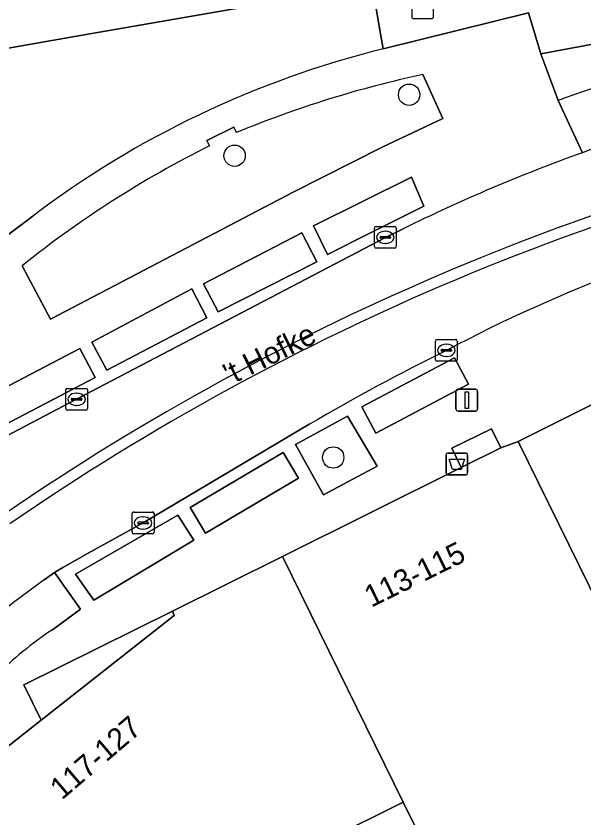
# Model space of a CAD drawing. Extents: x 162879 to 165540, y 384011 to 385181.
# Drawn here: x 164083.04 to 164109.04, y 384464.13 to 384500.81 of the extents above; entities that cross this region are included whole.
import ezdxf

# ---------------------------------------------------------------- set-up
doc = ezdxf.new("R2010")
doc.units = 0
for name, color, linetype in [('IMGEO_Afvalbak', 7, 'Continuous'), ('IMGEO_Boom', 7, 'Continuous'), ('IMGEO_Erf', 7, 'Continuous'), ('IMGEO_Groenvoorziening', 7, 'Continuous'), ('IMGEO_Kolk', 7, 'Continuous'), ('IMGEO_Lichtmast', 7, 'Continuous'), ('IMGEO_Openbare_ruimte_label', 7, 'Continuous'), ('IMGEO_Pand', 7, 'Continuous'), ('IMGEO_Pand_nummerreeks', 7, 'Continuous'), ('IMGEO_Pand_overbouw', 7, 'Continuous'), ('IMGEO_Parkeervlak_open', 7, 'Continuous'), ('IMGEO_Poller', 7, 'Continuous'), ('IMGEO_Rijbaan_lokaal_gesloten', 7, 'Continuous'), ('IMGEO_Rijbaan_lokaal_open', 7, 'Continuous'), ('IMGEO_Voetpad_open', 7, 'Continuous')]:
    doc.layers.add(name, color=color, linetype=linetype)

msp = doc.modelspace()

# ---------------------------------------------------------------- linework, layer by layer
at = {"layer": 'IMGEO_Afvalbak'}
for p, q in [((164102.726, 384479.923), (164102.726, 384480.723)), ((164102.726, 384480.723), (164102.726, 384479.923)), ((164102.826, 384480.823), (164103.616, 384480.823)), ((164103.616, 384480.823), (164102.826, 384480.823)), ((164103.716, 384480.723), (164103.716, 384479.923)), ((164103.716, 384479.923), (164103.716, 384480.723)), ((164103.616, 384479.823), (164102.826, 384479.823)), ((164102.826, 384479.823), (164103.616, 384479.823))]:
    msp.add_line(p, q, dxfattribs=at)
msp.add_lwpolyline([(164102.869, 384480.537), (164103.573, 384480.537), (164103.424, 384480.067), (164103.018, 384480.067), (164102.869, 384480.537)], dxfattribs=at)
for centre, start, end in [((164102.826, 384480.723), 90, 180), ((164102.826, 384480.723), 90, 180), ((164103.616, 384480.723), 0, 90), ((164103.616, 384480.723), 360, 90), ((164102.826, 384479.923), 180, 270), ((164102.826, 384479.923), 180, 270), ((164103.616, 384479.923), 270, 0), ((164103.616, 384479.923), 270, 0)]:
    msp.add_arc(centre, 0.1, start, end, dxfattribs=at)
at = {"layer": 'IMGEO_Boom'}
for centre in [(164101.039, 384497.213), (164093.047, 384494.422), (164097.562, 384480.618)]:
    msp.add_circle(centre, 0.489, dxfattribs=at)
at = {"layer": 'IMGEO_Erf'}
for points in [[(164099.846, 384499.31), (164099.728, 384500), (164096.988, 384516.038), (164096.451, 384515.965), (164098.837, 384502.169), (164086.427, 384500), (164076.77, 384498.312), (164077.06, 384496.833), (164073.548, 384494.062), (164079.048, 384490.02), (164080.722, 384491.873), (164082.275, 384490.508), (164083.808, 384491.663)], [(164104.315, 384457.699), (164100.767, 384464.846), (164093.655, 384461.316)]]:
    msp.add_lwpolyline(points, dxfattribs=at)
msp.add_arc((164110.43, 384456.471), 44.127, 103.8776, 127.1065, dxfattribs=at)
at = {"layer": 'IMGEO_Groenvoorziening'}
for points in [[(164119.508, 384500.11), (164119.28, 384501.365), (164107.065, 384499.079)], [(164107.065, 384499.079), (164107.867, 384496.956)], [(164084.62, 384486.95), (164095.737, 384492.755), (164099.806, 384494.82), (164102.58, 384496.132), (164101.668, 384498.136)], [(164093.138, 384495.481), (164093.014, 384495.726), (164091.778, 384495.123), (164091.906, 384494.876)], [(164083.322, 384489.384), (164084.62, 384486.95)], [(164084.807, 384475.359), (164084.33, 384475.022)], [(164084.714, 384472.739), (164085.996, 384473.68), (164084.807, 384475.359)]]:
    msp.add_lwpolyline(points, dxfattribs=at)
for points in [[(164101.715, 384492.119), (164101.149, 384493.443), (164096.663, 384491.211), (164097.295, 384489.901), (164099.277, 384490.9)], [(164097.117, 384478.912), (164099.578, 384480.214), (164098.21, 384482.512), (164095.832, 384481.212)]]:
    msp.add_lwpolyline(points, close=True, dxfattribs=at)
for centre, radius, start, end in [((164131.959, 384431.095), 70.129, 100.22681, 110.0926), ((164111.855, 384450.377), 48.834, 102.0408, 112.5372), ((164112.986, 384452.474), 47.353, 116.4338, 128.788), ((164106.482, 384443.885), 38.213, 125.4296, 135.8642), ((164093.11, 384459.914), 15.329, 123.2102, 135.8396)]:
    msp.add_arc(centre, radius, start, end, dxfattribs=at)
at = {"layer": 'IMGEO_Kolk'}
for p, q in [((164099.449, 384490.264), (164099.449, 384491.116)), ((164099.524, 384491.19), (164100.376, 384491.19)), ((164099.937, 384490.97), (164099.962, 384490.97)), ((164100.45, 384491.116), (164100.45, 384490.264)), ((164099.708, 384490.684), (164099.708, 384490.696)), ((164100.146, 384490.647), (164099.748, 384490.647)), ((164099.751, 384490.733), (164100.149, 384490.733)), ((164100.192, 384490.696), (164100.192, 384490.684)), ((164100.376, 384490.19), (164099.524, 384490.19)), ((164099.96, 384490.41), (164099.935, 384490.41)), ((164102.242, 384485.092), (164102.242, 384485.944)), ((164102.317, 384486.018), (164103.169, 384486.018)), ((164102.73, 384485.798), (164102.755, 384485.798)), ((164103.243, 384485.944), (164103.243, 384485.092)), ((164102.501, 384485.512), (164102.501, 384485.524)), ((164102.939, 384485.475), (164102.541, 384485.475)), ((164102.544, 384485.561), (164102.942, 384485.561)), ((164102.985, 384485.524), (164102.985, 384485.512)), ((164103.169, 384485.018), (164102.317, 384485.018)), ((164102.753, 384485.238), (164102.728, 384485.238)), ((164085.317, 384482.854), (164085.317, 384483.706)), ((164085.392, 384483.78), (164086.244, 384483.78)), ((164085.805, 384483.56), (164085.83, 384483.56)), ((164086.318, 384483.706), (164086.318, 384482.854)), ((164085.576, 384483.274), (164085.576, 384483.286)), ((164086.014, 384483.237), (164085.616, 384483.237)), ((164085.619, 384483.323), (164086.017, 384483.323)), ((164086.06, 384483.286), (164086.06, 384483.274)), ((164085.828, 384483), (164085.803, 384483)), ((164086.244, 384482.78), (164085.392, 384482.78)), ((164088.359, 384477.198), (164088.359, 384478.05)), ((164088.434, 384478.124), (164089.286, 384478.124)), ((164089.36, 384478.05), (164089.36, 384477.198)), ((164088.661, 384477.667), (164089.059, 384477.667)), ((164088.847, 384477.904), (164088.872, 384477.904)), ((164088.618, 384477.618), (164088.618, 384477.63)), ((164089.056, 384477.581), (164088.658, 384477.581)), ((164088.87, 384477.344), (164088.845, 384477.344)), ((164089.102, 384477.63), (164089.102, 384477.618)), ((164089.286, 384477.124), (164088.434, 384477.124))]:
    msp.add_line(p, q, dxfattribs=at)
for points in [[(164099.449, 384490.264), (164099.449, 384491.116)], [(164099.524, 384491.19), (164100.376, 384491.19)], [(164100.45, 384491.116), (164100.45, 384490.264)], [(164100.376, 384490.19), (164099.524, 384490.19)], [(164102.242, 384485.092), (164102.242, 384485.944)], [(164102.317, 384486.018), (164103.169, 384486.018)], [(164103.243, 384485.944), (164103.243, 384485.092)], [(164103.169, 384485.018), (164102.317, 384485.018)], [(164085.317, 384482.854), (164085.317, 384483.706)], [(164085.392, 384483.78), (164086.244, 384483.78)], [(164086.318, 384483.706), (164086.318, 384482.854)], [(164086.244, 384482.78), (164085.392, 384482.78)], [(164088.359, 384477.198), (164088.359, 384478.05)], [(164088.434, 384478.124), (164089.286, 384478.124)], [(164089.36, 384478.05), (164089.36, 384477.198)], [(164089.286, 384477.124), (164088.434, 384477.124)]]:
    msp.add_lwpolyline(points, dxfattribs=at)
for centre, radius, start, end in [((164099.526, 384491.114), 0.0765, 91.552, 178.448), ((164099.526, 384491.114), 0.0765, 91.552, 178.448), ((164100.374, 384491.114), 0.0765, 1.552, 88.448), ((164100.374, 384491.114), 0.0765, 1.552, 88.448), ((164099.748, 384490.693), 0.0403, 85.8775, 175.7526), ((164099.745, 384490.683), 0.0366, 178.938, 274.7102), ((164100.149, 384490.69), 0.043, 264.8664, 352.4533), ((164100.153, 384490.695), 0.0386, 1.7309, 96.639), ((164099.526, 384490.266), 0.0765, 181.552, 268.448), ((164099.526, 384490.266), 0.0765, 181.552, 268.448), ((164100.374, 384490.266), 0.0765, 271.552, 358.448), ((164100.374, 384490.266), 0.0765, 271.552, 358.448), ((164102.319, 384485.942), 0.0765, 91.552, 178.448), ((164102.319, 384485.942), 0.0765, 91.552, 178.448), ((164103.167, 384485.942), 0.0765, 1.552, 88.448), ((164103.167, 384485.942), 0.0765, 1.552, 88.448), ((164102.541, 384485.521), 0.0403, 85.8775, 175.7526), ((164102.538, 384485.511), 0.0366, 178.938, 274.7102), ((164102.942, 384485.518), 0.043, 264.8664, 352.4533), ((164102.946, 384485.523), 0.0386, 1.7309, 96.639), ((164102.319, 384485.094), 0.0765, 181.552, 268.448), ((164102.319, 384485.094), 0.0765, 181.552, 268.448), ((164103.167, 384485.094), 0.0765, 271.552, 358.448), ((164103.167, 384485.094), 0.0765, 271.552, 358.448), ((164085.394, 384483.704), 0.0765, 91.552, 178.448), ((164085.394, 384483.704), 0.0765, 91.552, 178.448), ((164086.242, 384483.704), 0.0765, 1.552, 88.448), ((164086.242, 384483.704), 0.0765, 1.552, 88.448), ((164085.616, 384483.283), 0.0403, 85.8775, 175.7526), ((164085.613, 384483.273), 0.0366, 178.938, 274.7102), ((164086.017, 384483.28), 0.043, 264.8664, 352.4533), ((164086.021, 384483.285), 0.0386, 1.7309, 96.639), ((164085.394, 384482.856), 0.0765, 181.552, 268.448), ((164085.394, 384482.856), 0.0765, 181.552, 268.448), ((164086.242, 384482.856), 0.0765, 271.552, 358.448), ((164086.242, 384482.856), 0.0765, 271.552, 358.448), ((164088.436, 384478.048), 0.0765, 91.552, 178.448), ((164088.436, 384478.048), 0.0765, 91.552, 178.448), ((164089.284, 384478.048), 0.0765, 1.552, 88.448), ((164089.284, 384478.048), 0.0765, 1.552, 88.448), ((164088.658, 384477.627), 0.0403, 85.8775, 175.7526), ((164089.063, 384477.629), 0.0386, 1.7309, 96.639), ((164088.655, 384477.617), 0.0366, 178.938, 274.7102), ((164089.059, 384477.624), 0.043, 264.8664, 352.4533), ((164088.436, 384477.2), 0.0765, 181.552, 268.448), ((164088.436, 384477.2), 0.0765, 181.552, 268.448), ((164089.284, 384477.2), 0.0765, 271.552, 358.448), ((164089.284, 384477.2), 0.0765, 271.552, 358.448)]:
    msp.add_arc(centre, radius, start, end, dxfattribs=at)
for centre, major_axis, ratio, start_param, end_param in [((164099.936, 384490.69), (-0.387, 0.002), 0.722429, 4.712389, 7.853982), ((164099.961, 384490.69), (-0.39, 0.002), 0.717154, 1.570796, 4.712389), ((164102.729, 384485.518), (-0.387, 0.002), 0.722429, 4.712389, 7.853982), ((164102.754, 384485.518), (-0.39, 0.002), 0.717154, 1.570796, 4.712389), ((164085.804, 384483.28), (-0.387, 0.002), 0.722429, 4.712389, 7.853982), ((164085.829, 384483.28), (-0.39, 0.002), 0.717154, 1.570796, 4.712389), ((164088.846, 384477.624), (-0.387, 0.002), 0.722429, 4.712389, 7.853982), ((164088.871, 384477.624), (-0.39, 0.002), 0.717154, 1.570796, 4.712389)]:
    msp.add_ellipse(centre, major_axis=major_axis, ratio=ratio, start_param=start_param, end_param=end_param, dxfattribs=at)
at = {"layer": 'IMGEO_Lichtmast'}
for p, q in [((164103.181, 384482.84), (164103.181, 384483.64)), ((164103.181, 384483.64), (164103.181, 384482.84)), ((164103.281, 384483.74), (164104.071, 384483.74)), ((164104.071, 384483.74), (164103.281, 384483.74)), ((164104.171, 384483.64), (164104.171, 384482.84)), ((164104.171, 384482.84), (164104.171, 384483.64)), ((164104.071, 384482.74), (164103.281, 384482.74)), ((164103.281, 384482.74), (164104.071, 384482.74))]:
    msp.add_line(p, q, dxfattribs=at)
msp.add_lwpolyline([(164103.601, 384483.615), (164103.751, 384483.615), (164103.751, 384482.865), (164103.601, 384482.865), (164103.601, 384483.615)], dxfattribs=at)
for centre, start, end in [((164103.281, 384483.64), 90, 180), ((164103.281, 384483.64), 90, 180), ((164104.071, 384483.64), 0, 90), ((164104.071, 384483.64), 360, 90), ((164103.281, 384482.84), 180, 270), ((164103.281, 384482.84), 180, 270), ((164104.071, 384482.84), 270, 0), ((164104.071, 384482.84), 270, 0)]:
    msp.add_arc(centre, 0.1, start, end, dxfattribs=at)
at = {"layer": 'IMGEO_Pand'}
for points in [[(164076.77, 384498.312), (164086.427, 384500), (164098.837, 384502.169), (164096.451, 384515.965), (164093.509, 384515.415), (164093.89, 384513.546), (164077.184, 384510.646), (164070.33, 384509.456), (164070.393, 384509.093), (164071.977, 384500), (164072.362, 384497.789), (164072.404, 384497.549)], [(164095.246, 384476.092), (164100.767, 384464.846), (164104.315, 384457.699), (164116.14, 384463.569), (164110.825, 384474.323), (164109.759, 384473.791), (164106.025, 384481.355), (164105.235, 384481.061), (164103.422, 384480.161)], [(164095.046, 384452.059), (164089.995, 384462.234), (164092.565, 384463.51), (164093.655, 384461.316), (164100.767, 384464.846), (164095.246, 384476.092), (164090.203, 384473.589), (164090.286, 384473.393), (164084.202, 384468.608), (164081.227, 384466.269), (164081.4, 384465.909), (164080.878, 384465.649), (164081.604, 384464.184), (164079.608, 384463.197), (164082.653, 384451.818), (164083.416, 384448.962)]]:
    msp.add_lwpolyline(points, close=True, dxfattribs=at)
at = {"layer": 'IMGEO_Pand_overbouw'}
msp.add_lwpolyline([(164084.202, 384468.608), (164090.286, 384473.393), (164090.203, 384473.589), (164083.402, 384470.224)], close=True, dxfattribs=at)
at = {"layer": 'IMGEO_Parkeervlak_open'}
for points in [[(164096.12, 384490.897), (164091.627, 384488.568), (164092.294, 384487.284), (164096.81, 384489.565)], [(164091.781, 384487.005), (164091.086, 384488.334), (164086.514, 384485.898), (164087.2, 384484.608)], [(164081.464, 384483.256), (164082.134, 384481.921), (164086.662, 384484.271), (164085.971, 384485.602)], [(164103.757, 384483.971), (164103.122, 384485.174), (164098.878, 384482.932), (164099.513, 384481.729)], [(164095.279, 384480.84), (164091.02, 384478.323), (164091.712, 384477.152), (164095.971, 384479.669)], [(164086.609, 384474.089), (164091.187, 384476.831), (164090.451, 384477.975), (164085.762, 384475.286)]]:
    msp.add_lwpolyline(points, close=True, dxfattribs=at)
at = {"layer": 'IMGEO_Poller'}
for p, q in [((164101.157, 384501.598), (164101.157, 384500.791)), ((164101.157, 384501.598), (164101.157, 384500.791)), ((164102.153, 384500.791), (164102.153, 384501.598)), ((164102.153, 384500.791), (164102.153, 384501.598)), ((164101.251, 384500.696), (164102.059, 384500.696)), ((164101.251, 384500.696), (164102.059, 384500.696))]:
    msp.add_line(p, q, dxfattribs=at)
for centre, start, end in [((164101.251, 384500.791), 180, 270), ((164101.251, 384500.791), 180, 270), ((164102.059, 384500.791), 270, 0), ((164102.059, 384500.791), 270, 0)]:
    msp.add_arc(centre, 0.0946, start, end, dxfattribs=at)
at = {"layer": 'IMGEO_Rijbaan_lokaal_gesloten'}
for points in [[(164100.758, 384491.073), (164099.95, 384490.69), (164085.818, 384483.28), (164081.711, 384481.132), (164079.691, 384480.076)], [(164084.33, 384475.022), (164084.807, 384475.359), (164085.219, 384475.594), (164086.352, 384476.247), (164088.86, 384477.624), (164096.5, 384482.153)]]:
    msp.add_lwpolyline(points, dxfattribs=at)
for centre, radius, start, end in [((164147.723, 384382.935), 115.303, 101.15181, 124.45379), ((164147.171, 384384.062), 113.554, 100.98769, 124.55292), ((164135.169, 384421.663), 77.466, 108.54321, 109.76939), ((164135.463, 384420.84), 78.34, 109.76871, 116.29617), ((164135.506, 384423.55), 70.096, 103.08436, 117.8656), ((164148.621, 384392.929), 103.332, 116.35821, 120.29145), ((164106.482, 384443.885), 38.213, 125.4296, 135.8642)]:
    msp.add_arc(centre, radius, start, end, dxfattribs=at)
at = {"layer": 'IMGEO_Rijbaan_lokaal_open'}
msp.add_lwpolyline([(164119.047, 384466.705), (164117.994, 384466.52), (164112.445, 384477.691), (164109.594, 384483.138), (164106.025, 384481.355), (164109.759, 384473.791), (164110.825, 384474.323), (164116.14, 384463.569), (164104.315, 384457.699), (164105.63, 384454.833), (164120.011, 384458.704)], close=True, dxfattribs=at)
for centre, radius, start, end in [((164147.723, 384382.935), 115.303, 101.15181, 124.45379), ((164147.171, 384384.062), 113.554, 100.98769, 124.55292)]:
    msp.add_arc(centre, radius, start, end, dxfattribs=at)
at = {"layer": 'IMGEO_Voetpad_open'}
for points in [[(164096.988, 384516.038), (164099.728, 384500), (164099.846, 384499.31), (164106.497, 384500.959)], [(164106.497, 384500.959), (164107.065, 384499.079), (164119.28, 384501.365), (164119.508, 384500.11)], [(164107.867, 384496.956), (164107.065, 384499.079), (164106.497, 384500.959), (164099.846, 384499.31)], [(164101.668, 384498.136), (164102.58, 384496.132), (164099.806, 384494.82), (164095.737, 384492.755), (164084.62, 384486.95)], [(164108.967, 384494.563), (164107.867, 384496.956)], [(164107.867, 384496.956), (164108.967, 384494.563)], [(164091.906, 384494.876), (164091.778, 384495.123), (164093.014, 384495.726), (164093.138, 384495.481)], [(164083.808, 384491.663), (164082.275, 384490.508), (164080.633, 384488.889), (164079.047, 384486.941), (164075.059, 384483.197)], [(164066.822, 384471.709), (164069.712, 384474.018), (164068.354, 384476.445), (164080.706, 384482.968), (164081.711, 384481.132), (164085.818, 384483.28), (164099.95, 384490.69), (164100.758, 384491.073)], [(164084.62, 384486.95), (164083.322, 384489.384)], [(164082.113, 384470.593), (164079.11, 384467.513), (164077.48, 384468.756), (164075.268, 384466.013), (164077.724, 384463.522), (164078.385, 384464.04), (164081.227, 384466.269), (164084.202, 384468.608), (164083.402, 384470.224), (164090.203, 384473.589), (164095.246, 384476.092), (164103.422, 384480.161), (164102.988, 384481.042), (164104.804, 384481.935), (164105.235, 384481.061), (164106.025, 384481.355), (164109.594, 384483.138)], [(164096.5, 384482.153), (164088.86, 384477.624), (164086.352, 384476.247), (164085.219, 384475.594), (164084.807, 384475.359), (164085.996, 384473.68), (164084.714, 384472.739)]]:
    msp.add_lwpolyline(points, dxfattribs=at)
for points in [[(164096.663, 384491.211), (164101.149, 384493.443), (164101.715, 384492.119), (164099.277, 384490.9), (164097.295, 384489.901)], [(164096.12, 384490.897), (164096.81, 384489.565), (164092.294, 384487.284), (164091.627, 384488.568)], [(164091.781, 384487.005), (164087.2, 384484.608), (164086.514, 384485.898), (164091.086, 384488.334)], [(164086.662, 384484.271), (164082.134, 384481.921), (164081.464, 384483.256), (164085.971, 384485.602)], [(164098.878, 384482.932), (164103.122, 384485.174), (164103.757, 384483.971), (164099.513, 384481.729)], [(164097.117, 384478.912), (164095.832, 384481.212), (164098.21, 384482.512), (164099.578, 384480.214)], [(164103.422, 384480.161), (164105.235, 384481.061), (164104.804, 384481.935), (164102.988, 384481.042)], [(164091.712, 384477.152), (164091.02, 384478.323), (164095.279, 384480.84), (164095.971, 384479.669)], [(164086.609, 384474.089), (164085.762, 384475.286), (164090.451, 384477.975), (164091.187, 384476.831)], [(164083.402, 384470.224), (164084.202, 384468.608), (164090.286, 384473.393), (164090.203, 384473.589)]]:
    msp.add_lwpolyline(points, close=True, dxfattribs=at)
for centre, radius, start, end in [((164131.959, 384431.095), 70.129, 100.22681, 110.0926), ((164110.43, 384456.471), 44.127, 103.8776, 127.1065), ((164111.855, 384450.377), 48.834, 102.0408, 112.5372), ((164135.169, 384421.663), 77.466, 108.54321, 109.76939), ((164112.986, 384452.474), 47.353, 116.4338, 128.788), ((164135.463, 384420.84), 78.34, 109.76871, 116.29617), ((164135.506, 384423.55), 70.096, 103.08436, 117.8656), ((164148.621, 384392.929), 103.332, 116.35821, 120.29145), ((164093.11, 384459.914), 15.329, 123.2102, 135.8396)]:
    msp.add_arc(centre, radius, start, end, dxfattribs=at)

# ---------------------------------------------------------------- texts
at = {"layer": 'IMGEO_Openbare_ruimte_label'}
msp.add_text("'t Hofke", height=1, rotation=26.4882, dxfattribs=at).set_placement((164092.855, 384483.913))
at = {"layer": 'IMGEO_Pand_nummerreeks'}
for s, rotation, p in [('113-115', 26.3088, (164099.308, 384473.74)), ('117-127', 40.5325, (164085.14, 384464.92))]:
    msp.add_text(s, height=1, rotation=rotation, dxfattribs=at).set_placement(p)

doc.saveas('drawing.dxf')
